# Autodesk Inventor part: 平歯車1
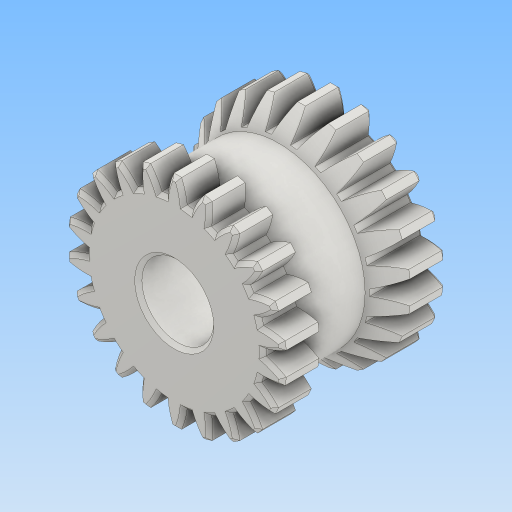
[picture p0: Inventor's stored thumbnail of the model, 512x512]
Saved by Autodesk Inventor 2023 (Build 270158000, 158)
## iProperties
CustomPartVersion: 1
Created: 2024-01
Part Number: 平歯車1
Material: Steel
Document SubType Name: Modeling
Designer: kumagai
Categories: <?xml version="1.0" encoding="UTF-16"?> <MemberInstance><Categories><FamilyTemplate><FamilyTemplateParameter ValueType="xs:double" Id="1" ObjectReferenceKey="da
Density: 1 g/cm^3
Appearance: Steel
Author: kumagai
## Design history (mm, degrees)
sketch "Sketch1"
  geometry: C1 r 12 at (0, 0)
  constraints: 1 centre point
  dimensions: "d0" = 24 diameter of C1 (= da_da)
extrude "Extrusion1" new body sketch "Sketch1" distance "d1" = 18 (= da_b); taper "d2" = 0 deg
workplane "Work Plane2"
sketch "Sketch2"
  geometry: C1 r 12 at (0, 0) reference; C2 r 11 at (0, 0)
  constraints: 1 centre point, 1 coincident
  dimensions: "d3" = 22 diameter of C2 (= da_d)
feature "ピッチ円直径" sketch "Sketch2" dims "d4" = 10, "d5" = 0
workplane "Work Plane8"
workplane "Work Plane9"
feature "平歯車" dims "da_b" = 18, "da_d" = 22, "da_aw" = 22, "da_da" = 24, "da_df" = 19.5, "da_dw" = 22, angle "da_beta" = 0 deg, "da_lefttooth" = 0, "da_righttooth" = 0
sketch "スケッチ3"
  geometry: L1 (0, -3.6)-(0, 21.6) reference; L2 (-24, 0)-(4, 0) reference; L3 (0, 0)-(-3.95, 0); L4 (-3.95, 0)-(-3.95, 18); L5 (-3.95, 18)-(0, 18); L6 (0, 18)-(0, 0); L7 (-12, 0)-(-20, 0); L8 (-20, 0)-(-20, 18); L9 (-20, 18)-(-12, 18); L10 (-12, 0)-(-12, 4); L11 (-12, 4)-(-9.5, 6.5); L12 (-9.5, 6.5)-(-9.5, 14); L13 (-9.5, 14)-(-12, 14); L14 (-12, 14)-(-12, 18); L15 (-9.5, 14)-(-9.5, 14); 2 further points
  constraints: 26 end point, 3 parallel, 3 point on line, 2 collinear, 2 horizontal, 2 perpendicular, 2 vertical
  dimensions: "d49" = 3.95 distance between parallel lines of L4 L1; "d50" = 18 distance between parallel lines of L7 L9; "d51" = 2.5 distance between parallel lines of L10 L12; "d52" = 4 distance from line of L7 L10.end; "d53" = 4 distance from line of L13.end L9; "d54" = 2.5 distance of L13.end L13.start; "d55" = 2.5 horizontal distance of L10.end L11.end; "d56" = 45 deg angle of L13 L15; "d57" = 9.5 distance between parallel lines of L12 L1; "d58" = 20 distance between parallel lines of L1 L8
revolve "回転1" sketch "スケッチ3" stored, may be unused: angle "d59" = 90 deg
chamfer "面取り1" distance "d60" = 0.4; stored, may be unused: second distance "d61" = 2, angle "d62" = 45 deg
body "Solid1"
body "Srf1"
other parameters: "d16" = 22 (= da_aw), "d17" = 0, "d34" = 1.428 (computed from da_z), "d39" = 0, "d41" = 0, "d43" = 22 (= da_aw), "d46" = 22 (= da_aw), "d47" = 0, "d48" = 0
